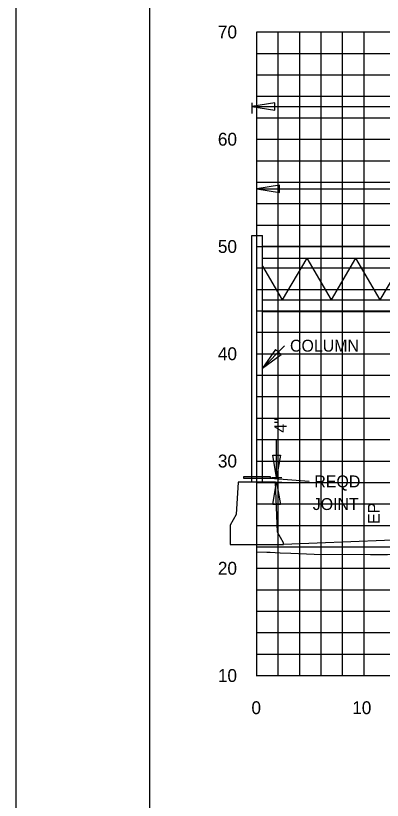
# Model space of a CAD drawing. Extents: x 2193008 to 2198143, y 1236112 to 1237864.
# Drawn here: x 2195562.2 to 2195596.4, y 1237151.5 to 1237224.6 of the extents above; entities that cross this region are included whole.
import ezdxf

# ---------------------------------------------------------------- set-up
doc = ezdxf.new("R2010")
doc.units = 0
for name, color, linetype in [('3', 7, 'Continuous'), ('31', 7, 'Continuous'), ('60', 7, 'Continuous'), ('Default', 7, 'Continuous'), ('GSDIMS', 7, 'Continuous'), ('Level 55', 7, 'Continuous'), ('LIMT-CSLINE', 7, 'Continuous'), ('M-ROADS', 7, 'Continuous'), ('SHT-BNDRY', 7, 'Continuous')]:
    doc.layers.add(name, color=color, linetype=linetype)

msp = doc.modelspace()

# ---------------------------------------------------------------- linework, layer by layer
msp.add_lwpolyline([(2195574.707, 1237133.046), (2195874.707, 1237133.046), (2195874.707, 1237323.046), (2195574.707, 1237323.046)], close=True)
at = {"layer": '3'}
for p, q in [((2195584.245, 1237216.501), (2195584.245, 1237215.491)), ((2195584.245, 1237216.154), (2195679.319, 1237216.154)), ((2195584.245, 1237181.134), (2195584.245, 1237204.12)), ((2195585.245, 1237181.134), (2195585.245, 1237204.12)), ((2195585.245, 1237191.753), (2195587.278, 1237193.849)), ((2195586.551, 1237181.578), (2195586.551, 1237185.132)), ((2195589.58, 1237181.189), (2195585.96, 1237181.489)), ((2195586.069, 1237181.578), (2195587.052, 1237181.578)), ((2195586.069, 1237181.134), (2195587.052, 1237181.134))]:
    msp.add_line(p, q, dxfattribs=at)
msp.add_lwpolyline([(2195585.96, 1237181.489), (2195583.492, 1237181.489), (2195583.492, 1237181.667), (2195585.96, 1237181.667)], close=True, dxfattribs=at)
at = {"layer": '60'}
for p, q in [((2195584.707, 1237163.106), (2195584.707, 1237223.106)), ((2195584.707, 1237163.046), (2195584.707, 1237163.106)), ((2195584.707, 1237163.106), (2195714.707, 1237163.106)), ((2195594.707, 1237163.046), (2195594.707, 1237163.106))]:
    msp.add_line(p, q, dxfattribs=at)
msp.add_lwpolyline([(2195587.2, 1237175.362), (2195596.632, 1237175.74), (2195608.634, 1237176.004), (2195619.956, 1237176.253), (2195631.956, 1237176.517), (2195643.956, 1237176.781), (2195657.692, 1237177.083), (2195669.692, 1237176.603), (2195671.692, 1237176.523), (2195675.192, 1237176.383), (2195690.656, 1237171.228)], dxfattribs=at)
at = {"layer": 'Default'}
msp.add_lwpolyline([(2195587.187, 1237175.31), (2195587.207, 1237175.31), (2195587.187, 1237175.48), (2195586.637, 1237176.48), (2195586.437, 1237181.134), (2195582.977, 1237181.134), (2195582.777, 1237178.134), (2195582.227, 1237177.134), (2195582.206, 1237176.964), (2195582.227, 1237175.31)], close=True, dxfattribs=at)
at = {"layer": 'GSDIMS'}
for p, q in [((2195584.707, 1237208.482), (2195612.713, 1237208.482)), ((2195584.245, 1237204.12), (2195585.245, 1237204.12)), ((2195585.245, 1237203.12), (2195612.713, 1237203.12)), ((2195585.245, 1237202.009), (2195612.713, 1237202.009)), ((2195589.361, 1237202.009), (2195587.083, 1237198.147)), ((2195589.361, 1237202.009), (2195591.64, 1237198.147)), ((2195593.918, 1237202.009), (2195591.64, 1237198.147)), ((2195593.918, 1237202.009), (2195596.197, 1237198.147)), ((2195598.475, 1237202.009), (2195596.197, 1237198.147)), ((2195585.245, 1237201.262), (2195587.083, 1237198.147)), ((2195585.245, 1237198.147), (2195614.457, 1237198.147)), ((2195585.245, 1237197.036), (2195614.457, 1237197.036))]:
    msp.add_line(p, q, dxfattribs=at)
for points in [[(2195584.245, 1237216.154), (2195586.373, 1237215.807), (2195586.373, 1237216.501)], [(2195584.707, 1237208.482), (2195586.835, 1237208.135), (2195586.835, 1237208.829)], [(2195585.245, 1237191.753), (2195586.968, 1237193.025), (2195586.453, 1237193.503)], [(2195586.551, 1237181.578), (2195586.196, 1237183.661), (2195586.906, 1237183.661)], [(2195586.551, 1237181.134), (2195586.906, 1237179.051), (2195586.196, 1237179.051)]]:
    msp.add_lwpolyline(points, close=True, dxfattribs=at)
at = {"layer": 'M-ROADS'}
for p, q in [((2195584.707, 1237223.106), (2195714.707, 1237223.106)), ((2195586.707, 1237163.106), (2195586.707, 1237223.106)), ((2195588.707, 1237163.106), (2195588.707, 1237223.106)), ((2195590.707, 1237163.106), (2195590.707, 1237223.106)), ((2195592.707, 1237163.106), (2195592.707, 1237223.106)), ((2195594.707, 1237163.106), (2195594.707, 1237223.106)), ((2195584.707, 1237221.106), (2195714.707, 1237221.106)), ((2195584.707, 1237219.106), (2195714.707, 1237219.106)), ((2195584.707, 1237217.106), (2195714.707, 1237217.106)), ((2195584.707, 1237215.106), (2195714.707, 1237215.106)), ((2195584.707, 1237213.106), (2195714.707, 1237213.106)), ((2195584.707, 1237211.106), (2195714.707, 1237211.106)), ((2195584.707, 1237209.106), (2195714.707, 1237209.106)), ((2195584.707, 1237207.106), (2195714.707, 1237207.106)), ((2195584.707, 1237205.106), (2195714.707, 1237205.106)), ((2195584.707, 1237203.106), (2195714.707, 1237203.106)), ((2195584.707, 1237201.106), (2195714.707, 1237201.106)), ((2195584.707, 1237199.106), (2195714.707, 1237199.106)), ((2195584.707, 1237197.106), (2195714.707, 1237197.106)), ((2195584.707, 1237195.106), (2195714.707, 1237195.106)), ((2195584.707, 1237193.106), (2195714.707, 1237193.106)), ((2195584.707, 1237191.106), (2195714.707, 1237191.106)), ((2195584.707, 1237189.106), (2195714.707, 1237189.106)), ((2195584.707, 1237187.106), (2195714.707, 1237187.106)), ((2195584.707, 1237185.106), (2195714.707, 1237185.106)), ((2195584.707, 1237183.106), (2195714.707, 1237183.106)), ((2195584.707, 1237181.106), (2195714.707, 1237181.106)), ((2195584.707, 1237179.106), (2195714.707, 1237179.106)), ((2195584.707, 1237177.106), (2195714.707, 1237177.106)), ((2195584.707, 1237175.106), (2195714.707, 1237175.106)), ((2195584.707, 1237173.106), (2195714.707, 1237173.106)), ((2195584.707, 1237171.106), (2195714.707, 1237171.106)), ((2195584.707, 1237169.106), (2195714.707, 1237169.106)), ((2195584.707, 1237167.106), (2195714.707, 1237167.106)), ((2195584.707, 1237165.106), (2195714.707, 1237165.106)), ((2195584.707, 1237163.106), (2195714.707, 1237163.106))]:
    msp.add_line(p, q, dxfattribs=at)
msp.add_lwpolyline([(2195584.707, 1237174.638), (2195585.628, 1237174.618), (2195585.966, 1237174.599), (2195586.873, 1237174.555), (2195587.872, 1237174.51), (2195590.054, 1237174.412), (2195595.308, 1237174.402), (2195596.894, 1237174.4), (2195599.516, 1237174.504), (2195600.392, 1237174.538), (2195600.737, 1237174.552), (2195601.636, 1237174.58), (2195608.061, 1237174.725), (2195613.203, 1237174.839), (2195615.685, 1237174.891), (2195625.468, 1237175.06), (2195627.311, 1237175.07), (2195637.121, 1237175.142), (2195643.667, 1237175.037), (2195649.033, 1237174.936), (2195657.92, 1237174.726), (2195662.188, 1237174.616)], dxfattribs=at)
at = {"layer": 'SHT-BNDRY'}
msp.add_lwpolyline([(2195562.21, 1237123.036), (2195884.71, 1237123.036), (2195884.71, 1237333.036), (2195562.21, 1237333.036)], close=True, dxfattribs=at)

# ---------------------------------------------------------------- texts
at = {"layer": '31'}
for s, p in [('70', (2195581.073, 1237222.506)), ('60', (2195581.073, 1237212.506)), ('50', (2195581.073, 1237202.506)), ('40', (2195581.073, 1237192.506)), ('30', (2195581.073, 1237182.506)), ('20', (2195581.073, 1237172.506)), ('10', (2195581.073, 1237162.506))]:
    msp.add_text(s, height=1.2, dxfattribs=at).set_placement(p)
at = {"layer": 'Level 55'}
for s, p in [('COLUMN', (2195587.801, 1237193.3)), ('REQD', (2195590.073, 1237180.648)), ('JOINT', (2195589.925, 1237178.537))]:
    msp.add_text(s, height=1.1105, dxfattribs=at).set_placement(p)
for s, height, p in [('4"', 1.1346, (2195587.477, 1237185.74)), ('EP', 1.1105, (2195596.18, 1237177.235))]:
    msp.add_text(s, height=height, rotation=90, dxfattribs=at).set_placement(p)
at = {"layer": 'LIMT-CSLINE'}
for s, p in [('0', (2195584.206, 1237159.506)), ('10', (2195593.606, 1237159.506))]:
    msp.add_text(s, height=1.2, dxfattribs=at).set_placement(p)

doc.saveas('drawing.dxf')
